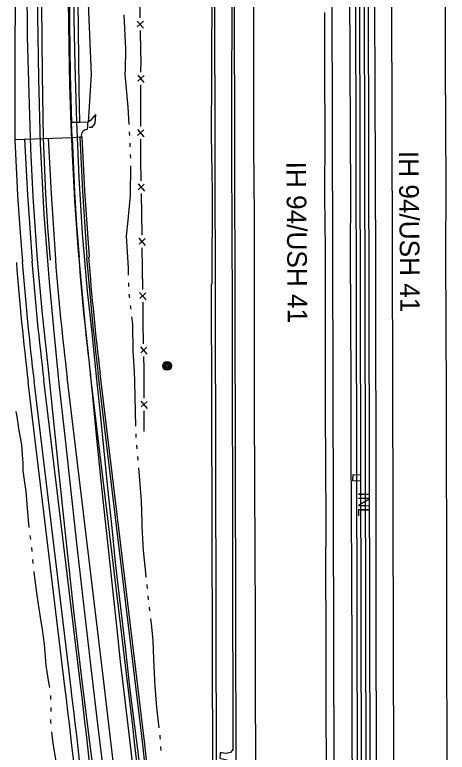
# Model space of a CAD drawing. Extents: x 588843 to 2552415, y 180129 to 269402.
# Drawn here: x 593837.9 to 594058.9, y 184808.3 to 185185.1 of the extents above; entities that cross this region are included whole.
import ezdxf

# ---------------------------------------------------------------- set-up
doc = ezdxf.new("R2010")
doc.units = 0
for name, color, linetype in [('E_DRN', 7, 'Continuous'), ('E_DRN_RipRap', 7, 'Continuous'), ('E_DRN_Text', 7, 'Continuous'), ('E_FEN_P', 7, 'Continuous'), ('E_MISCPROP', 7, 'Continuous'), ('E_RDWY', 7, 'Continuous'), ('E_RDWY_AsphConc', 7, 'Continuous'), ('E_RDWY_BarrierConc', 7, 'Continuous'), ('E_RDWY_C_and_G', 7, 'Continuous'), ('E_RDWY_Gravel', 7, 'Continuous'), ('E_RDWY_PavtEdge', 7, 'Continuous'), ('E_RDWY_Text', 7, 'Continuous'), ('E_STRUCT', 7, 'Continuous'), ('E_STRUCT_Joint', 7, 'Continuous'), ('E_WTR_P', 7, 'Continuous'), ('P_RDWY_BarrierConc', 7, 'Continuous'), ('P_RDWY_C_and_G', 7, 'Continuous'), ('P_RDWY_C_and_GBack', 7, 'Continuous'), ('P_RDWY_C_and_GFace', 7, 'Continuous'), ('P_RDWY_LaneEdge', 7, 'Continuous'), ('P_RDWY_PavtEdge', 7, 'Continuous'), ('P_RDWY_ShldAgg', 7, 'Continuous'), ('P_RDWY_ShldPaved', 7, 'Continuous')]:
    doc.layers.add(name, color=color, linetype=linetype)

# ---------------------------------------------------------------- blocks, each defined once
blk = doc.blocks.new('INLT_47_1')
at = {"layer": 'E_DRN_Text'}
blk.add_text('INL', height=39.37, dxfattribs=at).set_placement((-36.2, -19.7))
blk = doc.blocks.new('POLE_3')
at = {"layer": 'E_MISCPROP'}
for radius in [14.6, 11, 7.32, 3.66]:
    blk.add_circle((0, 0), radius, dxfattribs=at)

msp = doc.modelspace()

# ---------------------------------------------------------------- linework, layer by layer
at = {"layer": 'E_DRN'}
msp.add_lwpolyline([(594014.54, 184946.89), (594010.66, 184947.03), (594010.77, 184950.18), (594014.65, 184950.05)], close=True, dxfattribs=at)
at = {"layer": 'E_DRN_RipRap'}
for points in [[(593879.08, 185134.14), (593876.68, 185131.35), (593875.43, 185130.24)], [(593879.08, 185134.14), (593878.73, 185129.8), (593877.32, 185127.48), (593875.98, 185127.45)]]:
    msp.add_lwpolyline(points, dxfattribs=at)
at = {"layer": 'E_FEN_P'}
for p, q in [((593900.41, 185181.93), (593903.68, 185178.3)), ((593903.62, 185181.82), (593900.52, 185178.99)), ((593900.73, 185154.21), (593903.93, 185150.51)), ((593903.94, 185154.03), (593900.78, 185151.26)), ((593900.62, 185126.46), (593903.82, 185122.75)), ((593903.84, 185126.27), (593900.68, 185123.51)), ((593900.88, 185098.67), (593904.15, 185095.03)), ((593904.1, 185098.55), (593900.99, 185095.73)), ((593901.3, 185070.92), (593904.56, 185067.28)), ((593904.51, 185070.8), (593901.41, 185067.98)), ((593901.71, 185043.17), (593904.97, 185039.53)), ((593904.92, 185043.05), (593901.82, 185040.22)), ((593902.12, 185015.42), (593905.39, 185011.77)), ((593905.33, 185015.3), (593902.23, 185012.47)), ((593902.36, 184987.68), (593905.6, 184984)), ((593905.58, 184987.52), (593902.45, 184984.73))]:
    msp.add_line(p, q, dxfattribs=at)
for points in [[(593901.68, 185194.19), (593901.86, 185183.59)], [(593901.98, 185177.03), (593902.16, 185166.43)], [(593902.16, 185166.43), (593902.24, 185161.74), (593902.22, 185155.84)], [(593902.19, 185149.28), (593902.15, 185138.68)], [(593902.15, 185138.68), (593902.11, 185128.08)], [(593902.09, 185121.52), (593902.08, 185118.48), (593902.19, 185110.92)], [(593902.19, 185110.92), (593902.34, 185100.33)], [(593902.44, 185093.77), (593902.6, 185083.17)], [(593902.6, 185083.17), (593902.76, 185072.57)], [(593902.85, 185066.01), (593903.01, 185055.42)], [(593903.01, 185055.42), (593903.17, 185044.82)], [(593903.26, 185038.26), (593903.42, 185027.67)], [(593903.42, 185027.67), (593903.58, 185017.07)], [(593903.67, 185010.51), (593903.77, 185004.35), (593903.79, 184999.91)], [(593903.79, 184999.91), (593903.84, 184989.31)], [(593903.87, 184982.75), (593903.93, 184972.16)]]:
    msp.add_lwpolyline(points, dxfattribs=at)
at = {"layer": 'E_RDWY'}
for points in [[(594023.34, 184682.26), (594023.25, 184709.56), (594023.04, 184739.91), (594023, 184778.2), (594022.82, 184818.16), (594022.67, 184861.06), (594022.65, 184896.86), (594022.58, 184934.07), (594022.62, 184972.8), (594022.48, 185013.2), (594022.39, 185057.62), (594022.2, 185103.22), (594022.12, 185147.96), (594021.99, 185189.79), (594021.86, 185234.19), (594021.61, 185282.87), (594021.71, 185325.21), (594022.01, 185370.2), (594022.14, 185393.45)], [(594058.92, 184785.01), (594058.82, 184814.32), (594058.74, 184856.48), (594058.72, 184888.42), (594058.64, 184920.39), (594058.61, 184955.57), (594058.47, 184990.54), (594058.38, 185026.41), (594058.18, 185063.12), (594058.32, 185096.32), (594058.13, 185129.63), (594058.04, 185158.77), (594058.03, 185187.99), (594057.99, 185226.54), (594057.97, 185253.66), (594057.64, 185280.67), (594057.82, 185338.96), (594057.67, 185356.32), (594057.68, 185378.51)], [(593906.33, 184603.12), (593902.92, 184632.27), (593899.65, 184660.76), (593895.88, 184692.09), (593892.24, 184722.03), (593889.11, 184748.84), (593886.03, 184775.27), (593883.34, 184797.63), (593880.29, 184822.58), (593876.81, 184852.9), (593873.76, 184879.56), (593870.15, 184910.6), (593867.01, 184938.51), (593863.39, 184971.22), (593860.52, 184996.66), (593857.95, 185023.1), (593855.61, 185048.62), (593852.95, 185083.15), (593851.06, 185119.17), (593850.2, 185152.54), (593849.72, 185184.93), (593849.66, 185210.92)], [(593961.66, 184584.71), (593961.61, 184597.79), (593961.51, 184627.2), (593961.41, 184654.59), (593961.38, 184693.93), (593961.28, 184727.64), (593961.06, 184762.04), (593961.05, 184801.45), (593960.9, 184844.07), (593960.93, 184878.06), (593960.81, 184909.45), (593960.59, 184947.71), (593960.4, 184982.2), (593960.44, 185016.64), (593960.35, 185048.64), (593960.38, 185082.04), (593960.11, 185118.13), (593960.11, 185156.58), (593960.05, 185202.8)], [(593865.21, 185192.03), (593865.51, 185169.15), (593865.94, 185149.26), (593866.52, 185128.73), (593867.31, 185110.37), (593868.41, 185090.32), (593870.11, 185066.19), (593872.08, 185044.12), (593873.76, 185027.55), (593875.68, 185008.73), (593877.73, 184988.23), (593879.49, 184970.25), (593881.85, 184946.98), (593883.87, 184927.75), (593885.79, 184910.94), (593887.78, 184891.64), (593890.07, 184871.2), (593891.83, 184854.69), (593894.51, 184832.02), (593897.19, 184809.08), (593899.84, 184786.18)], [(593997.74, 184579.23), (593997.88, 184602.77), (593997.66, 184636.35), (593997.62, 184658.68), (593997.56, 184689.47), (593997.45, 184718.98), (593997.28, 184748.08), (593997.28, 184776.99), (593997.26, 184803.01), (593997.03, 184828.04), (593997.04, 184853.56), (593997.01, 184872.9), (593996.93, 184898.91), (593996.95, 184927.32), (593996.91, 184954.55), (593996.75, 184983.68), (593996.74, 185009.24), (593996.75, 185039.17), (593996.69, 185065.27), (593996.43, 185092.39), (593996.46, 185124.29), (593996.36, 185155.17), (593996.3, 185186.28)]]:
    msp.add_lwpolyline(points, dxfattribs=at)
at = {"layer": 'E_RDWY_AsphConc'}
for points in [[(593880.44, 185453.26), (593877.09, 185432.82), (593874.68, 185401.65), (593869.68, 185351.53), (593868.04, 185328.52), (593868.59, 185305.06), (593869.44, 185252.63), (593869.98, 185207.15), (593870.24, 185177.47), (593870.68, 185147.16), (593871.02, 185130.16)], [(593835.51, 185420.49), (593834.36, 185418.93), (593835.27, 185400.95), (593838.25, 185354.97), (593839.96, 185330.69), (593839.05, 185305.69), (593838.39, 185254.46), (593838.17, 185204.09), (593837.95, 185155.65), (593837.92, 185121.35)], [(593837.92, 185121.35), (593852.41, 185121.99), (593867.21, 185122.36), (593866.82, 185130.11)], [(593872.08, 185122.79), (593871.99, 185123.86), (593872.27, 185124.89), (593872.88, 185125.77), (593872.88, 185125.77), (593873.89, 185126.44), (593875.07, 185126.67), (593875.07, 185126.67), (593875.29, 185128.17), (593875.23, 185129.26), (593875.17, 185130.25), (593871.02, 185130.16), (593866.82, 185130.11)], [(593837.92, 185121.35), (593839.35, 185093), (593839.35, 185093), (593840.51, 185075.96), (593841.87, 185058.93), (593841.87, 185058.93)]]:
    msp.add_lwpolyline(points, dxfattribs=at)
at = {"layer": 'E_RDWY_BarrierConc'}
msp.add_lwpolyline([(593937.96, 185372.16), (593938.03, 185339.45), (593938.08, 185303.3), (593938.5, 185252.99), (593938.55, 185202.16), (593938.47, 185154.12), (593938.23, 185123.59), (593938.78, 185094.92), (593938.68, 185047.47)], dxfattribs=at)
at = {"layer": 'E_RDWY_C_and_G'}
for points in [[(593867.21, 185122.36), (593871.12, 185122.73), (593872.08, 185122.79)], [(593867.21, 185122.36), (593868.4, 185094.46), (593868.4, 185094.46), (593869.47, 185077.76), (593870.83, 185061.07), (593870.83, 185061.07)], [(593871.12, 185122.73), (593872.44, 185094.93), (593872.44, 185094.93), (593874.77, 185061.12), (593874.77, 185061.12)], [(593872.08, 185122.79), (593873.49, 185095.1), (593873.49, 185095.1), (593875.89, 185061.23), (593875.89, 185061.23)]]:
    msp.add_lwpolyline(points, dxfattribs=at)
at = {"layer": 'E_RDWY_Gravel'}
for points in [[(593880.55, 185453.99), (593880.27, 185436.18), (593879.73, 185413.27), (593873.51, 185372.17), (593873.98, 185339.4), (593872.71, 185305.48), (593873.23, 185253.41), (593874.93, 185203.22), (593876.95, 185154.58), (593875.43, 185130.24)], [(593903.57, 184787.84), (593900.04, 184815.06), (593896.94, 184840.13), (593894.47, 184862.21), (593891.84, 184883.59), (593889.43, 184905.22), (593887.61, 184922.97), (593885.5, 184943.38), (593883.62, 184962.33), (593881.65, 184981.18), (593879.68, 185000.31), (593877.36, 185022.6), (593875.03, 185043.96), (593872.53, 185073.32), (593870.8, 185101.96), (593869.67, 185130.47), (593868.77, 185159.23), (593868.28, 185183.24), (593868.29, 185205.46)], [(593901.51, 184604.7), (593898.89, 184628.12), (593894.48, 184661.7), (593891.4, 184689.97), (593887.19, 184723.53), (593883.88, 184751.61), (593880.49, 184781.82), (593876.8, 184809.14), (593872.09, 184846.12), (593868.13, 184880.53), (593863.95, 184918.6), (593860.69, 184948.98), (593857.26, 184982.17), (593854.92, 185005.52), (593852.06, 185032.14), (593849.54, 185060.16), (593847.3, 185092.17), (593846.04, 185116.76), (593845.29, 185144.85), (593844.4, 185173.99), (593844.28, 185200.35)], [(593949.5, 184809.8), (593948.2, 184808.25), (593945.74, 184807.72), (593943.63, 184807.97), (593942.94, 184808.04), (593942.74, 184805.25), (593947.41, 184804.12), (593950.05, 184802.84), (593950.73, 184802.31), (593951.07, 184775.26), (593950.85, 184747.91), (593950.97, 184721.39), (593951.02, 184689.79), (593951.09, 184659.68), (593951.11, 184632.56), (593951.21, 184602.44), (593951.27, 184588.18)]]:
    msp.add_lwpolyline(points, dxfattribs=at)
at = {"layer": 'E_RDWY_PavtEdge'}
for points in [[(593875.85, 185453.59), (593873.92, 185432.86), (593870.99, 185400.68), (593866.59, 185351.79), (593864.42, 185328.6), (593864.71, 185305.3), (593865.19, 185252.78), (593865.69, 185207.57), (593865.81, 185180.99), (593866.2, 185154.42), (593866.2, 185154.42), (593866.82, 185130.11), (593866.82, 185130.11)], [(593839.4, 185400.62), (593842.88, 185354.87), (593846.48, 185307.23), (593850.58, 185253.42), (593851.31, 185207.69), (593851.9, 185154.74), (593851.9, 185154.74), (593852.41, 185121.99), (593852.41, 185121.99), (593853.62, 185093.61), (593853.62, 185093.61), (593854.67, 185076.65), (593855.94, 185059.71), (593855.94, 185059.71)]]:
    msp.add_lwpolyline(points, dxfattribs=at)
at = {"layer": 'E_STRUCT'}
for points in [[(593949.5, 184809.8), (593949.49, 184844.07), (593949.38, 184874.99), (593949.34, 184910.76), (593949.25, 184952.33), (593949.24, 184977.34), (593949.2, 185005.39), (593949.13, 185032.79), (593948.99, 185077.15), (593948.89, 185110.83), (593948.85, 185154.41), (593949.04, 185179.37), (593949.06, 185215.53), (593948.81, 185257.23), (593948.62, 185298.71), (593948.49, 185342.33), (593948.21, 185388.66), (593948.33, 185405.71), (593947.89, 185415.89)], [(594007.57, 185399.67), (594008.45, 185379.96), (594008.58, 185346.39), (594008.62, 185302.69), (594008.59, 185270.63), (594008.85, 185235.62), (594008.95, 185198.53), (594009.16, 185161.43), (594009.23, 185125.36), (594009.42, 185092.69), (594009.24, 185064.46), (594009.4, 185031), (594009.61, 184996.11), (594009.68, 184962.18), (594009.8, 184932.13), (594009.91, 184898.48), (594010.17, 184858.49), (594010.07, 184823.02), (594010.32, 184787.4), (594010.45, 184753.11), (594010.69, 184718.6), (594010.65, 184679.45), (594010.55, 184642.38), (594010.12, 184601.49)]]:
    msp.add_lwpolyline(points, dxfattribs=at)
at = {"layer": 'E_STRUCT_Joint'}
for points in [[(593842.91, 185121.56), (593844.32, 185093.11), (593846.79, 185059.12)], [(593855, 185122.02), (593856.47, 185093.67), (593856.47, 185093.67), (593858.76, 185060.18), (593858.76, 185060.18)]]:
    msp.add_lwpolyline(points, dxfattribs=at)
at = {"layer": 'E_WTR_P'}
for points in [[(593893.63, 185185.09), (593894.49, 185167.66), (593894.24, 185157.09)], [(593894.24, 185157.09), (593894.19, 185154.85), (593895.59, 185137.9), (593896.11, 185129.15)], [(593896.34, 185125.29), (593896.44, 185123.36)], [(593896.63, 185119.5), (593896.72, 185117.57)], [(593896.91, 185113.71), (593897, 185111.78)], [(593897.02, 185107.92), (593896.86, 185092.72), (593895.62, 185079.96)], [(593895.62, 185079.96), (593894.86, 185072.21), (593895.84, 185055.69), (593895.92, 185052.01)], [(593896, 185048.14), (593896.05, 185046.21)], [(593896.26, 185042.35), (593896.47, 185040.43)], [(593896.91, 185036.59), (593897.13, 185034.67)], [(593897.56, 185030.83), (593897.99, 185027.06), (593898.22, 185013.28), (593898.85, 185002.86)], [(593898.85, 185002.86), (593899.14, 184997.98), (593899.41, 184982.04), (593899.61, 184974.85)], [(593838.5, 184982.46), (593838.92, 184979.88), (593839.86, 184973.67), (593841.29, 184965.38), (593841.67, 184960.26), (593841.95, 184956.18), (593842.06, 184952.84)], [(593899.72, 184970.99), (593899.77, 184969.06)], [(593900.08, 184965.21), (593900.24, 184963.28)], [(593900.57, 184959.43), (593900.73, 184957.51)], [(593842.06, 184952.83), (593842.07, 184952.25), (593842.71, 184947.31), (593843.46, 184941.51), (593844.57, 184928.79), (593845.07, 184923.12)], [(593901.06, 184953.65), (593902.5, 184936.8), (593902.75, 184925.7)], [(593902.75, 184925.7), (593902.8, 184923.41), (593903.44, 184911.34), (593904.94, 184898.21), (593904.98, 184897.79)], [(593845.62, 184919.04), (593845.96, 184917)], [(593846.4, 184912.91), (593846.59, 184910.86)], [(593846.99, 184906.75), (593847.19, 184904.7)], [(593847.61, 184900.6), (593847.8, 184898.71), (593849.16, 184888.58), (593850.74, 184878.29), (593851.83, 184871.03)], [(593905.35, 184893.94), (593905.54, 184892.02)], [(593905.91, 184888.18), (593906.1, 184886.25)], [(593906.54, 184882.41), (593906.76, 184880.5)], [(593907.22, 184876.66), (593907.55, 184873.91), (593908.42, 184865.57), (593908.84, 184855.72), (593909.12, 184848.73)], [(593851.83, 184871.03), (593852.96, 184863.46), (593853.83, 184852.66), (593855.12, 184844.03), (593855.58, 184841.41)], [(593909.12, 184848.72), (593909.4, 184841.84), (593910.26, 184831.2), (593911.52, 184820.83)], [(593856.13, 184837.33), (593856.18, 184835.28)], [(593856.3, 184831.16), (593856.31, 184830.58), (593856.28, 184829.1)], [(593856.19, 184824.98), (593856.16, 184823.82), (593856.24, 184822.92)], [(593856.64, 184818.82), (593857.32, 184812.83), (593859.06, 184802.75), (593860.6, 184789.22)], [(593911.98, 184816.99), (593912.09, 184816.07), (593912.15, 184815.07)], [(593912.35, 184811.21), (593912.45, 184809.28)]]:
    msp.add_lwpolyline(points, dxfattribs=at)
at = {"layer": 'P_RDWY_BarrierConc'}
for p, q in [((594015.52, 183703.15), (594011.71, 185400.89)), ((594017.52, 183703.15), (594013.71, 185400.03)), ((594020.02, 183703.16), (594016.21, 185398.95)), ((594022.02, 183703.16), (594018.21, 185398.08)), ((593941.13, 184768.81), (593939.74, 185387.02)), ((593939.13, 184768.81), (593938.5, 185047.43))]:
    msp.add_line(p, q, dxfattribs=at)
at = {"layer": 'P_RDWY_C_and_G'}
msp.add_line((593895.31, 184845.72), (593876.53, 185001.32), dxfattribs=at)
for centre, radius, start, end in [((595281.34, 185170.82), 1415, 184.45717, 186.8799), ((585838.74, 183873.64), 8115, 4.312666, 6.879896)]:
    msp.add_arc(centre, radius, start, end, dxfattribs=at)
at = {"layer": 'P_RDWY_C_and_GBack'}
msp.add_line((593900.27, 184846.32), (593881.5, 185001.92), dxfattribs=at)
for centre, radius, start, end in [((595281.34, 185170.82), 1410, 184.45873, 186.8799), ((585838.74, 183873.64), 8120, 4.310168, 6.879896)]:
    msp.add_arc(centre, radius, start, end, dxfattribs=at)
at = {"layer": 'P_RDWY_C_and_GFace'}
msp.add_line((593899.28, 184846.2), (593880.5, 185001.8), dxfattribs=at)
for centre, radius, start, end in [((595281.34, 185170.82), 1411, 184.45841, 186.8799), ((585838.74, 183873.64), 8119, 4.310168, 6.879896)]:
    msp.add_arc(centre, radius, start, end, dxfattribs=at)
at = {"layer": 'P_RDWY_LaneEdge'}
msp.add_line((593883.39, 184844.28), (593864.62, 184999.88), dxfattribs=at)
for centre, radius, start, end in [((595281.34, 185170.82), 1427, 184.45348, 186.8799), ((585838.74, 183873.64), 8103, 4.245358, 6.879896)]:
    msp.add_arc(centre, radius, start, end, dxfattribs=at)
at = {"layer": 'P_RDWY_PavtEdge'}
for p, q in [((594003.52, 183703.12), (593999.78, 185371.14)), ((594034.02, 183703.19), (594030.35, 185336.23)), ((593871.48, 184842.85), (593852.7, 184998.44))]:
    msp.add_line(p, q, dxfattribs=at)
for centre, radius, start, end in [((595281.34, 185170.82), 1439, 184.44984, 186.8799), ((585838.74, 183873.64), 8091, 6.154981, 6.879896)]:
    msp.add_arc(centre, radius, start, end, dxfattribs=at)
at = {"layer": 'P_RDWY_ShldAgg'}
msp.add_line((593863.54, 184841.89), (593844.76, 184997.49), dxfattribs=at)
for centre, radius, start, end in [((595281.34, 185170.82), 1447, 184.44746, 186.8799), ((585838.74, 183873.64), 8083, 6.154981, 6.879896)]:
    msp.add_arc(centre, radius, start, end, dxfattribs=at)
at = {"layer": 'P_RDWY_ShldPaved'}
for p, q in [((593951.77, 184483.94), (593949.78, 185371.03)), ((593866.51, 184842.25), (593847.74, 184997.85))]:
    msp.add_line(p, q, dxfattribs=at)
for centre, radius, start, end in [((595281.34, 185170.82), 1444, 184.44835, 186.8799), ((585838.74, 183873.64), 8086, 6.154981, 6.879896)]:
    msp.add_arc(centre, radius, start, end, dxfattribs=at)

# ---------------------------------------------------------------- block references
at = {"layer": 'E_DRN_Text', "xscale": 0.1524003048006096, "yscale": 0.1524003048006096, "rotation": -90.21819803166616}
msp.add_blockref('INLT_47_1', (594016.4, 184935.74), dxfattribs=at)
at = {"layer": 'E_MISCPROP', "xscale": 0.1524003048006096, "yscale": 0.15240030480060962, "rotation": -84.36014555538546}
msp.add_blockref('POLE_3', (593915.7, 185005.7), dxfattribs=at)

# ---------------------------------------------------------------- texts
at = {"layer": 'E_RDWY_Text'}
for p in [(594034.2, 185115.53), (593976.7, 185110.04)]:
    msp.add_text('IH 94/USH 41', height=10, rotation=270.5073, dxfattribs=at).set_placement(p)

doc.saveas('drawing.dxf')
